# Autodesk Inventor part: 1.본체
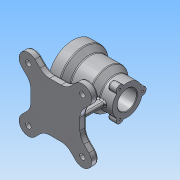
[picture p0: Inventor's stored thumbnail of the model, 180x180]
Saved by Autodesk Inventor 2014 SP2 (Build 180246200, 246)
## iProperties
Created: 2017-03
Part Number: 1.본체
Material: 알루미늄 6061
Document SubType Name: Modeling
Designer: SDA
Density: 2.71 g/cm^3
Appearance: 알루미늄 - 평지
Author: SDA
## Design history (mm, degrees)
sketch "스케치1"
  geometry: L1 (0, 0)-(100, 0); L2 (0, 0)-(0, 45); L3 (0, 45)-(20, 45); L4 (20, 45)-(31, 36); L5 (31, 36)-(65, 36); L6 (65, 36)-(77, 27.5); L7 (77, 27.5)-(100, 27.5); L8 (100, 27.5)-(100, 0)
  constraints: 16 end point, 4 horizontal, 2 vertical
  dimensions: "d0" = 100 distance of L1.start L1.end; "d1" = 90 diameter of L3 L1; "d2" = 72 diameter of L5 L1; "d3" = 55 diameter of L7 L1; "d4" = 20 distance of L2.end L3.end; "d5" = 31 distance from line of L4.end L2; "d6" = 65 distance from line of L2 L5.end; "d7" = 23 distance from line of L8 L6.end
revolve "회전1" sketch "스케치1" stored, may be unused: angle "d8" = 90 deg
sketch "스케치2"
  geometry: C1 r 35 at (0, 0); C2 r 45 at (0, 0) reference
  constraints: 1 centre point, 1 coincident
  dimensions: "d9" = 70 diameter of C1
extrude "돌출1" cut sketch "스케치2" distance "d10" = 23; taper "d11" = 0 deg
sketch "스케치4"
  geometry: C1 r 35 at (0, 0) reference; C2 r 26 at (0, 0)
  constraints: 1 centre point, 1 coincident
  dimensions: "d12" = 52 diameter of C2
extrude "돌출2" cut sketch "스케치4" distance "d13" = 47; taper "d14" = 0 deg
sketch "스케치5"
  geometry: C1 r 26 at (0, 0) reference; C2 r 17.5 at (0, 0)
  constraints: 1 centre point, 1 coincident
  dimensions: "d15" = 35 diameter of C2
extrude "돌출3" cut sketch "스케치5" distance "d16" = 30; taper "d17" = 0 deg
sketch "스케치6"
  geometry: C1 r 17.5 at (0, 0) reference; A1 r 7 centre (0, 27.5) between (6.943, 26.609) and (-6.943, 26.609); A2 r 27.5 centre (0, 0) between (-6.943, 26.609) and (6.943, 26.609) reference; A3 r 27.5 centre (0, 0) between (6.943, 26.609) and (-6.943, 26.609); A4 r 7 centre (-23.816, -13.75) between (-26.516, -7.292) and (-19.573, -19.317); A5 r 27.5 centre (0, 0) between (-26.516, -7.292) and (-19.573, -19.317); A6 r 7 centre (23.816, -13.75) between (19.573, -19.317) and (26.516, -7.292); A7 r 27.5 centre (0, 0) between (19.573, -19.317) and (26.516, -7.292); 1 further point
  constraints: 14 point on circle, 6 centre point, 1 coincident, 1 vertical alignment, 19 other
  dimensions: "d18" = 14 diameter of A1; "d19" = 27.5 distance of point (0, 0) A1.centre; "d23" = 360 deg dimension on A2.centre A1.centre (derived)
extrude "돌출4" join sketch "스케치6" distance "d25" = 15; taper "d26" = 0 deg
sketch "스케치7"
  geometry: A1 r 7 centre (0, 0) between (6.943, -0.891) and (-6.943, -0.891) reference; 1 further point
  constraints: 1 coincident
hole "구멍1" sketch "스케치7" at (0, 0) diameter "d27" = 3.459; stored, may be unused: countersink angle "d31" = 90 deg, drill point angle "d33" = 118 deg; dims "d28" = 9, "d29" = 4, "d30" = 2, "d32" = 11
sketch "스케치8"
  geometry: C1 r 35 at (0, 0) reference; 1 further point
  constraints: 1 vertical alignment
  dimensions: "d38" = 40 distance of C1.centre point (0, 40)
hole "구멍2" sketch "스케치8" at (0, 40) diameter "d39" = 3.459; stored, may be unused: countersink angle "d43" = 90 deg, drill point angle "d45" = 118 deg; dims "d40" = 9, "d41" = 4, "d42" = 2, "d44" = 11
node "작업 평면1"
sketch "스케치9"
  geometry: L1 (-11, 1.73)-(-12.039, 0) reference; L2 (-12.039, 0)-(-11, -1.73) reference; L3 (-11, -1.73)-(0, -1.73) reference; L4 (0, -1.73)-(0, -20.616) reference; L5 (0, -20.616)-(-20, -20.616) reference; L6 (-20, 20.616)-(0, 20.616) reference; L7 (0, 20.616)-(0, 1.73) reference; L8 (0, 1.73)-(-11, 1.73) reference; L9 (-31, 36)-(-65, 36) reference; L10 (-31, -36)-(-65, -36) reference; L11 (-100, 27.5)-(-100, 6.943) reference; C1 r 5 at (-50, 0); 2 further points
  constraints: 1 centre point, 1 vertical alignment
  dimensions: "d50" = 10 diameter of C1; "d51" = 36 distance from line of L9 C1.centre; "d52" = 50 distance from line of C1.centre L11
extrude "돌출5" join sketch "스케치9" stored distance "d53" = 15; taper "d54" = 0 deg
hole "구멍3" diameter "d57" = 4.459; stored, may be unused: countersink angle "d61" = 90 deg, drill point angle "d63" = 118 deg; dims "d58" = 14, "d59" = 4, "d60" = 2, "d62" = 14, "d174" = 10, "d175" = 10
node "작업 평면2"
sketch "스케치11"
  geometry: L1 (-10.072, 0)-(98.226, 0); L2 (11.518, 37.477)-(2.322, 28.281); L3 (-12.523, 61.518)-(-21.719, 52.322); L4 (-5, 0)-(-5, 10.603); L5 (-87.477, 61.518)-(-78.281, 52.322); L6 (-111.518, 37.477)-(-102.322, 28.281); L7 (-95, 0)-(-95, 10.603); L8 (-50, 45)-(-39.397, 45); L9 (-50, 45)-(-60.603, 45); L10 (11.518, -37.477)-(2.322, -28.281); L11 (-12.523, -61.518)-(-21.719, -52.322); L12 (-50, -45)-(-39.397, -45); L13 (-50, -45)-(-60.603, -45); L14 (-87.477, -61.518)-(-78.281, -52.322); L15 (-111.518, -37.477)-(-102.322, -28.281); L16 (-95, 0)-(-95, -10.603); L17 (-5, 0)-(-5, -10.603); C1 r 5 at (-50, 0) reference; C2 r 2.229 at (-50, 0) reference; A1 r 17 centre (-0.503, 49.497) between (11.518, 37.477) and (-13.894, 59.97); A2 r 25 centre (20, 10.603) between (2.322, 28.281) and (-5, 10.603); A3 r 17 centre (-99.497, 49.497) between (-87.477, 61.518) and (-111.518, 37.477); A4 r 25 centre (-120, 10.603) between (-95, 10.603) and (-102.322, 28.281); A5 r 25 centre (-39.397, 70) between (-39.397, 45) and (-21.719, 52.322); A6 r 25 centre (-60.603, 70) between (-78.281, 52.322) and (-60.603, 45); A7 r 25 centre (20, -10.603) between (-5, -10.603) and (2.322, -28.281); A8 r 17 centre (-0.503, -49.497) between (-12.523, -61.518) and (11.518, -37.477); A9 r 25 centre (-39.397, -70) between (-21.719, -52.322) and (-39.397, -45); A10 r 25 centre (-60.603, -70) between (-60.603, -45) and (-78.281, -52.322); A11 r 25 centre (-120, -10.603) between (-102.322, -28.281) and (-95, -10.603); A12 r 17 centre (-99.497, -49.497) between (-111.518, -37.477) and (-87.477, -61.518); 12 further points
  constraints: 34 end point, 25 point on circle, 12 centre point, 6 tangent, 2 horizontal, 1 parallel, 1 perpendicular, 1 vertical
extrude "돌출6" join sketch "스케치11" distance "d153" = 12; taper "d154" = 0 deg
sketch "스케치12"
  geometry: C1 r 5 at (0.503, 49.497); C2 r 5 at (99.497, 49.497); C3 r 5 at (99.497, -49.497); C4 r 5 at (0.503, -49.497); A1 r 17 centre (0.503, -49.497) between (-11.518, -37.477) and (12.523, -61.518) reference; A2 r 17 centre (99.497, -49.497) between (87.477, -61.518) and (111.518, -37.477) reference; A3 r 17 centre (99.497, 49.497) between (111.518, 37.477) and (87.477, 61.518) reference; A4 r 17 centre (0.503, 49.497) between (12.523, 61.518) and (-11.518, 37.477) reference; 1 further point
  constraints: 4 centre point, 4 coincident
  dimensions: "d155" = 10 diameter of C1; "d156" = 10 diameter of C2; "d157" = 10 diameter of C3; "d158" = 10 diameter of C4
extrude "돌출7" cut sketch "스케치12" distance "d159" = 12; taper "d160" = 0 deg
node "작업 평면3"
sketch "스케치13"
  geometry: L1 (45, -70)-(45, -82) reference; L2 (45, -82)-(-45, -82) reference; L3 (-45, -82)-(-45, -70) reference; L4 (-45, -70)-(45, -70) reference; L5 (5, 40)-(5, 35.651) reference; L6 (-5, 40)-(-2.229, 40) reference; L7 (-5, 35.651)-(-5, 40) reference; L8 (2.229, 40)-(5, 40) reference; L9 (37.477, -70)-(28.281, -70) reference; L10 (45, -70)-(52.322, -70) reference; L11 (0, -72)-(25, -72); L12 (25, -72)-(16.841, -25.731); L13 (16.841, -25.731)-(0, -31.644); L14 (-16.841, -25.731)-(0, -31.644); L15 (-25, -72)-(-16.841, -25.731); L16 (0, -72)-(-25, -72); L17 (-2.229, 40)-(-2.229, 26) reference; L18 (-2.229, 26)-(-2.09, 25.916) reference; L19 (2.09, 25.916)-(2.229, 26) reference; L20 (2.229, 26)-(2.229, 40) reference; A1 r 26 centre (0, 0) between (-2.09, 25.916) and (2.09, 25.916) reference; A2 r 36 centre (0, 0) between (-5, 35.651) and (5, 35.651) reference; 4 further points
  constraints: 12 end point, 2 point on line, 1 horizontal
  dimensions: "d165" = 100 deg angle of L12 L11; "d166" = 25 distance of L11.start L11.end; "d167" = 72 distance of point (0, 0) L11.start; "d197" = 25 horizontal distance of L15.start L13.end
extrude "돌출8" join sketch "스케치13" stored distance "d168" = 8; taper "d169" = 0 deg
sketch "스케치14"
  geometry: L1 (100, 17.5)-(70, 17.5) reference; L2 (70, 17.5)-(70, 26) reference; L3 (70, 26)-(52.23, 26) reference; L4 (52.23, 26)-(52.23, 40) reference; L5 (52.23, 40)-(55, 40) reference; L6 (55, 40)-(55, 36) reference; L7 (55, 36)-(65, 36) reference; L8 (65, 36)-(77, 27.5) reference; L9 (77, 27.5)-(85, 27.5) reference; L10 (85, 27.5)-(85, 34.5) reference; L11 (85, 34.5)-(100, 34.5) reference; L12 (100, 34.5)-(100, 29.23) reference; L13 (100, 29.23)-(89, 29.23) reference; L14 (89, 29.23)-(87.961, 27.5) reference; L15 (87.961, 27.5)-(89, 25.77) reference; L16 (89, 25.77)-(100, 25.77) reference; L17 (100, 25.77)-(100, 17.5) reference; L18 (23, 35)-(0, 35) reference; L19 (0, 35)-(0, 38.27) reference; L20 (0, 38.27)-(11, 38.27) reference; L21 (11, 38.27)-(12.039, 40) reference; L22 (12.039, 40)-(11, 41.73) reference; L23 (11, 41.73)-(0, 41.73) reference; L24 (0, 41.73)-(0, 45) reference; L25 (0, 45)-(20, 45) reference; L26 (20, 45)-(31, 36) reference; L27 (31, 36)-(45, 36) reference; L28 (45, 36)-(45, 40) reference; L29 (45, 40)-(47.77, 40) reference; L30 (47.77, 40)-(47.77, 26) reference; L31 (47.77, 26)-(23, 26) reference; L32 (23, 26)-(23, 35) reference; L33 (95, -70)-(95, -82) reference; L34 (95, -82)-(5, -82) reference; L35 (5, -82)-(5, -70) reference; L36 (5, -70)-(46, -70) reference; L37 (46, -70)-(46, -36) reference; L38 (46, -36)-(31, -36) reference; L39 (31, -36)-(20, -45) reference; L40 (20, -45)-(0, -45) reference; L41 (0, -45)-(0, -41.73) reference; L42 (0, -41.73)-(11, -41.73) reference; L43 (11, -41.73)-(12.039, -40) reference; L44 (12.039, -40)-(11, -38.27) reference; L45 (11, -38.27)-(0, -38.27) reference; L46 (0, -38.27)-(0, -35) reference; L47 (0, -35)-(23, -35) reference; L48 (23, -35)-(23, -26) reference; L49 (23, -26)-(70, -26) reference; L50 (70, -26)-(70, -17.5) reference; L51 (70, -17.5)-(100, -17.5) reference; L52 (100, -17.5)-(100, -27.5) reference; L53 (100, -27.5)-(77, -27.5) reference; L54 (77, -27.5)-(65, -36) reference; L55 (65, -36)-(54, -36) reference; L56 (54, -36)-(54, -70) reference; L57 (54, -70)-(95, -70) reference; L58 (50, -76.825)-(13, -76.825); L59 (13, -76.825)-(13, -40.425); L60 (13, -40.425)-(20.552, -38.461); L61 (20.552, -38.461)-(30.234, -30.539); L62 (30.234, -30.539)-(58.394, -30.539); L63 (58.394, -30.539)-(87, -23.561); L64 (87, -23.561)-(87, -76.825)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; 1 further point
  constraints: 16 end point, 3 horizontal, 2 vertical, 1 parallel
  dimensions: "d191" = 37 distance of L58.start L58.end; "d192" = 37 distance of L58.start L64.end
  node "절단 모서리 투영5"
chamfer "모따기1" distance "d176" = 1; stored, may be unused: second distance "d177" = 2, angle "d178" = 45 deg
fillet "모깎기1" dims "d179" = 3
fillet "모깎기2" dims "d180" = 3
fillet "모깎기3" dims "d181" = 3
fillet "모깎기4" dims "d182" = 1
sketch "스케치15"
  geometry: L1 (43, 21.072)-(43, -21.072) reference; L2 (49, -27.165)-(51, -27.165) reference; L3 (57, -21.072)-(57, 21.072) reference; L4 (51, 27.165)-(49, 27.165) reference; L5 (-9.397, 39.598)-(-0.201, 30.402) reference; L6 (8, 10.603)-(8, -10.603) reference; L7 (-0.201, -30.402)-(-9.397, -39.598) reference; L8 (10.402, -59.397)-(19.598, -50.201) reference; L9 (39.397, -42)-(60.603, -42) reference; L10 (80.402, -50.201)-(89.598, -59.397) reference; L11 (109.397, -39.598)-(100.201, -30.402) reference; L12 (92, -10.603)-(92, 10.603) reference; L13 (100.201, 30.402)-(109.397, 39.598) reference; L14 (89.598, 59.397)-(80.402, 50.201) reference; L15 (60.603, 42)-(39.397, 42) reference; L16 (19.598, 50.201)-(10.402, 59.397) reference; L17 (5, 10.603)-(5, -10.603) reference; C1 r 5 at (99.497, -49.497) reference; C2 r 5 at (0.503, 49.497) reference; C3 r 5 at (99.497, 49.497) reference; C4 r 5 at (0.503, -49.497) reference; A1 r 14 centre (0.503, 49.497) between (10.402, 59.397) and (-9.397, 39.598) reference; A2 r 28 centre (-20, 10.603) between (8, 10.603) and (-0.201, 30.402) reference; A3 r 28 centre (-20, -10.603) between (-0.201, -30.402) and (8, -10.603) reference; A4 r 14 centre (0.503, -49.497) between (-9.397, -39.598) and (10.402, -59.397) reference; A5 r 28 centre (39.397, -70) between (39.397, -42) and (19.598, -50.201) reference; A6 r 28 centre (60.603, -70) between (80.402, -50.201) and (60.603, -42) reference; A7 r 14 centre (99.497, -49.497) between (89.598, -59.397) and (109.397, -39.598) reference; A8 r 28 centre (120, -10.603) between (92, -10.603) and (100.201, -30.402) reference; A9 r 28 centre (120, 10.603) between (100.201, 30.402) and (92, 10.603) reference; A10 r 14 centre (99.497, 49.497) between (109.397, 39.598) and (89.598, 59.397) reference; A11 r 28 centre (60.603, 70) between (60.603, 42) and (80.402, 50.201) reference; A12 r 28 centre (39.397, 70) between (19.598, 50.201) and (39.397, 42) reference; 2 further points
  constraints: 5 other
  dimensions: "d184" = 45 distance from line of point (50, -35) L17; "d185" = 35 vertical distance of point (50, -35) point (0, 0)
feature "엠보싱1" sketch "스케치15" dims "d0" = 100, "d1" = 90, "d2" = 72, "d3" = 55, "d4" = 20, "d5" = 31, "d6" = 65, "d7" = 23, "d12" = 52, "d186" = 0.5, "d187" = 0
extrude "돌출10" join sketch "스케치14" stored distance "d193" = 8; taper "d194" = 0 deg
fillet "모깎기5" dims "d195" = 3
fillet "모깎기6" dims "d196" = 3
node "솔리드1"
pattern_circular "원형 패턴1" dims angle "d35" = 360 deg
pattern_circular "원형 패턴2" dims angle "d47" = 360 deg
node "절단 모서리 투영1"
node "절단 모서리 투영2"
node "절단 모서리 투영4"
node "절단 모서리 투영6"
other parameters: "d64" = -82, "d75" = 51.47524
